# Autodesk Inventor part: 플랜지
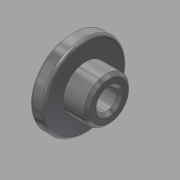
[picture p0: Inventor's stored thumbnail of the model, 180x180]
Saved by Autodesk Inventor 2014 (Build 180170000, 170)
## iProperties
Created: 2018-01
Part Number: 플랜지
Material: 스테인리스강
Document SubType Name: Modeling
Designer: mduedu
Density: 1 g/cm^3
Appearance: 반광택
Author: mduedu
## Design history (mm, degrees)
sketch "스케치1"
  geometry: L1 (0, 0)-(0, 7); L2 (0, 7)-(2.5, 7); L3 (2.5, 7)-(2.5, 3.75); L4 (2.5, 3.75)-(6.5, 3.75); L5 (6.5, 3.75)-(6.5, 0); L6 (6.5, 0)-(0, 0)
  constraints: 12 end point, 4 parallel, 1 perpendicular, 1 vertical
  dimensions: "d0" = 14 diameter of L2 L6; "d2" = 7.5 diameter of L4 L6; "d3" = 2.5 distance of L1.end L2.end; "d4" = 6.5 distance between parallel lines of L5 L1
revolve "회전1" sketch "스케치1" stored, may be unused: angle "d5" = 90 deg
hole "구멍1" diameter "d8" = 3.5; stored, may be unused: countersink angle "d12" = 90 deg, drill point angle "d14" = 118 deg; dims "d9" = 6, "d10" = 4, "d11" = 2, "d13" = 8, "d19" = 10, "d20" = 10
fillet "모깎기1" dims "d15" = 0.5
chamfer "모따기1" distance "d16" = 0.5; stored, may be unused: second distance "d17" = 2, angle "d18" = 45 deg
chamfer "모따기2" distance "d21" = 0.5; stored, may be unused: second distance "d22" = 2, angle "d23" = 45 deg
node "솔리드1"
